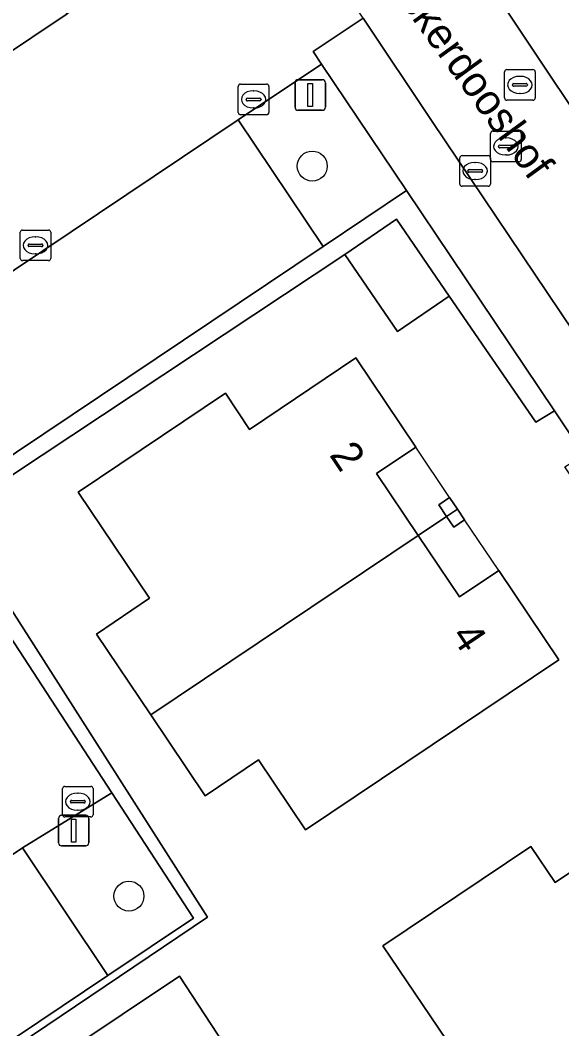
# Model space of a CAD drawing. Extents: x 158793 to 159888, y 384317 to 385256.
# Drawn here: x 159024.76 to 159042.44, y 384694.29 to 384727.22 of the extents above; entities that cross this region are included whole.
import ezdxf

# ---------------------------------------------------------------- set-up
doc = ezdxf.new("R2010")
doc.units = 0
for name, color, linetype in [('IMGEO_Boom', 7, 'Continuous'), ('IMGEO_Erf', 7, 'Continuous'), ('IMGEO_Groenvoorziening', 7, 'Continuous'), ('IMGEO_Haag', 7, 'Continuous'), ('IMGEO_Kolk', 7, 'Continuous'), ('IMGEO_Lichtmast', 7, 'Continuous'), ('IMGEO_Openbare_ruimte_label', 7, 'Continuous'), ('IMGEO_Pand', 7, 'Continuous'), ('IMGEO_Pand_nummerreeks', 7, 'Continuous'), ('IMGEO_Pand_overbouw', 7, 'Continuous'), ('IMGEO_Parkeervlak_open', 7, 'Continuous'), ('IMGEO_Rijbaan_lokaal_open', 7, 'Continuous'), ('IMGEO_Rioolput', 7, 'Continuous'), ('IMGEO_Voetpad_open', 7, 'Continuous')]:
    doc.layers.add(name, color=color, linetype=linetype)

msp = doc.modelspace()

# ---------------------------------------------------------------- linework, layer by layer
at = {"layer": 'IMGEO_Boom'}
for centre in [(159034.294, 384722.455), (159028.308, 384698.621)]:
    msp.add_circle(centre, 0.489, dxfattribs=at)
at = {"layer": 'IMGEO_Erf'}
msp.add_lwpolyline([(159055.318, 384693.517), (159052.491, 384697.775), (159053.123, 384698.213), (159052.175, 384699.623), (159051.584, 384699.252), (159048.706, 384703.383), (159047.007, 384702.243), (159045.317, 384704.764), (159043.638, 384707.269), (159045.328, 384708.423), (159042.543, 384712.634), (159043.163, 384713.033), (159042.202, 384714.463), (159041.598, 384714.096), (159038.77, 384718.208), (159037.078, 384717.054), (159035.359, 384719.573), (159022.492, 384711.051), (159024.718, 384707.573), (159030.87, 384697.932), (159016.999, 384688.587)], dxfattribs=at)
for points in [[(159040.385, 384709.248), (159042.345, 384706.334), (159034.075, 384700.783), (159032.538, 384703.066), (159030.794, 384701.892), (159029.02, 384704.535), (159027.246, 384707.177), (159028.983, 384708.347), (159026.647, 384711.814), (159031.457, 384715.04), (159032.247, 384713.86), (159035.716, 384716.191), (159037.675, 384713.278), (159036.397, 384712.419), (159037.756, 384710.399), (159039.106, 384708.393)], [(159039.269, 384710.907), (159038.917, 384710.67), (159038.679, 384711.019), (159038.424, 384711.393), (159038.781, 384711.633), (159039.034, 384711.257)], [(159047.656, 384698.482), (159046.366, 384697.618), (159047.711, 384695.583), (159049.055, 384693.548), (159050.34, 384694.411), (159052.295, 384691.502), (159043.979, 384685.926), (159042.461, 384688.214), (159040.71, 384687.044), (159038.89, 384689.755), (159037.159, 384692.334), (159038.938, 384693.537), (159036.601, 384696.993), (159041.436, 384700.241), (159042.229, 384699.061), (159045.709, 384701.391)], [(159036.569, 384683.938), (159034.328, 384682.412), (159035.518, 384680.598), (159032.519, 384678.557), (159030.179, 384682.029), (159028.896, 384681.167), (159027.613, 384680.304), (159030, 384676.764), (159027.005, 384674.748), (159025.717, 384676.65), (159023.432, 384675.127), (159022.331, 384676.771), (159021.158, 384675.986), (159017.982, 384680.739), (159020.712, 384682.584), (159021.88, 384683.374), (159019.249, 384687.3), (159026.926, 384692.448), (159026.219, 384693.503), (159029.956, 384696.009), (159033.245, 384690.989), (159032.277, 384690.34)]]:
    msp.add_lwpolyline(points, close=True, dxfattribs=at)
at = {"layer": 'IMGEO_Groenvoorziening'}
for points in [[(159031.875, 384723.961), (159034.645, 384719.834), (159037.367, 384721.658), (159034.599, 384725.777)], [(159035.359, 384719.573), (159037.05, 384720.727), (159038.77, 384718.208), (159041.598, 384714.096), (159042.202, 384714.463), (159037.367, 384721.658), (159034.645, 384719.834), (159021.882, 384711.279), (159024.421, 384707.105), (159027.752, 384701.991), (159030.413, 384697.906), (159027.614, 384696.029), (159017.072, 384688.957), (159016.845, 384688.805), (159016.999, 384688.587), (159030.87, 384697.932), (159024.718, 384707.573), (159022.492, 384711.051)], [(159027.752, 384701.991), (159024.836, 384700.201), (159027.614, 384696.029), (159030.413, 384697.906)]]:
    msp.add_lwpolyline(points, close=True, dxfattribs=at)
at = {"layer": 'IMGEO_Haag'}
msp.add_lwpolyline([(159037.367, 384721.658), (159034.645, 384719.834), (159021.882, 384711.279), (159024.421, 384707.105), (159027.752, 384701.991), (159030.413, 384697.906), (159027.614, 384696.029), (159017.072, 384688.957), (159016.845, 384688.805), (159016.999, 384688.587), (159030.87, 384697.932), (159024.718, 384707.573), (159022.492, 384711.051), (159035.359, 384719.573), (159037.05, 384720.727), (159038.77, 384718.208), (159041.598, 384714.096), (159042.202, 384714.463)], close=True, dxfattribs=at)
at = {"layer": 'IMGEO_Kolk'}
for p, q in [((159031.878, 384724.206), (159031.878, 384725.058)), ((159031.953, 384725.132), (159032.805, 384725.132)), ((159032.879, 384725.058), (159032.879, 384724.206)), ((159032.366, 384724.912), (159032.391, 384724.912)), ((159032.137, 384724.626), (159032.137, 384724.638)), ((159032.575, 384724.589), (159032.177, 384724.589)), ((159032.18, 384724.675), (159032.578, 384724.675)), ((159032.621, 384724.638), (159032.621, 384724.626)), ((159032.805, 384724.132), (159031.953, 384724.132)), ((159032.389, 384724.352), (159032.364, 384724.352)), ((159039.111, 384721.869), (159039.111, 384722.721)), ((159039.186, 384722.795), (159040.038, 384722.795)), ((159040.112, 384722.721), (159040.112, 384721.869)), ((159039.599, 384722.575), (159039.624, 384722.575)), ((159039.37, 384722.289), (159039.37, 384722.301)), ((159039.808, 384722.252), (159039.41, 384722.252)), ((159039.413, 384722.338), (159039.811, 384722.338)), ((159039.854, 384722.301), (159039.854, 384722.289)), ((159040.038, 384721.795), (159039.186, 384721.795)), ((159039.622, 384722.015), (159039.597, 384722.015)), ((159024.755, 384719.441), (159024.755, 384720.293)), ((159024.83, 384720.367), (159025.682, 384720.367)), ((159025.243, 384720.147), (159025.268, 384720.147)), ((159025.756, 384720.293), (159025.756, 384719.441)), ((159025.014, 384719.861), (159025.014, 384719.873)), ((159025.452, 384719.824), (159025.054, 384719.824)), ((159025.057, 384719.91), (159025.455, 384719.91)), ((159025.498, 384719.873), (159025.498, 384719.861)), ((159025.266, 384719.587), (159025.241, 384719.587)), ((159025.682, 384719.367), (159024.83, 384719.367)), ((159026.137, 384701.278), (159026.137, 384702.13)), ((159026.212, 384702.204), (159027.064, 384702.204)), ((159026.625, 384701.984), (159026.65, 384701.984)), ((159027.138, 384702.13), (159027.138, 384701.278)), ((159026.396, 384701.698), (159026.396, 384701.71)), ((159026.834, 384701.661), (159026.436, 384701.661)), ((159026.439, 384701.747), (159026.837, 384701.747)), ((159026.88, 384701.71), (159026.88, 384701.698)), ((159026.648, 384701.424), (159026.623, 384701.424)), ((159027.064, 384701.204), (159026.212, 384701.204))]:
    msp.add_line(p, q, dxfattribs=at)
for points in [[(159031.878, 384724.206), (159031.878, 384725.058)], [(159031.953, 384725.132), (159032.805, 384725.132)], [(159032.879, 384725.058), (159032.879, 384724.206)], [(159032.805, 384724.132), (159031.953, 384724.132)], [(159039.111, 384721.869), (159039.111, 384722.721)], [(159039.186, 384722.795), (159040.038, 384722.795)], [(159040.112, 384722.721), (159040.112, 384721.869)], [(159040.038, 384721.795), (159039.186, 384721.795)], [(159024.755, 384719.441), (159024.755, 384720.293)], [(159024.83, 384720.367), (159025.682, 384720.367)], [(159025.756, 384720.293), (159025.756, 384719.441)], [(159025.682, 384719.367), (159024.83, 384719.367)], [(159026.137, 384701.278), (159026.137, 384702.13)], [(159026.212, 384702.204), (159027.064, 384702.204)], [(159027.138, 384702.13), (159027.138, 384701.278)], [(159027.064, 384701.204), (159026.212, 384701.204)]]:
    msp.add_lwpolyline(points, dxfattribs=at)
for centre, radius, start, end in [((159031.955, 384725.056), 0.0765, 91.552, 178.448), ((159031.955, 384725.056), 0.0765, 91.552, 178.448), ((159032.803, 384725.056), 0.0765, 1.552, 88.448), ((159032.803, 384725.056), 0.0765, 1.552, 88.448), ((159032.177, 384724.635), 0.0403, 85.8775, 175.7526), ((159032.174, 384724.625), 0.0366, 178.938, 274.7102), ((159032.578, 384724.632), 0.043, 264.8664, 352.4533), ((159032.582, 384724.637), 0.0386, 1.7309, 96.639), ((159031.955, 384724.208), 0.0765, 181.552, 268.448), ((159031.955, 384724.208), 0.0765, 181.552, 268.448), ((159032.803, 384724.208), 0.0765, 271.552, 358.448), ((159032.803, 384724.208), 0.0765, 271.552, 358.448), ((159039.188, 384722.719), 0.0765, 91.552, 178.448), ((159039.188, 384722.719), 0.0765, 91.552, 178.448), ((159040.036, 384722.719), 0.0765, 1.552, 88.448), ((159040.036, 384722.719), 0.0765, 1.552, 88.448), ((159039.41, 384722.298), 0.0403, 85.8775, 175.7526), ((159039.407, 384722.288), 0.0366, 178.938, 274.7102), ((159039.811, 384722.295), 0.043, 264.8664, 352.4533), ((159039.815, 384722.3), 0.0386, 1.7309, 96.639), ((159039.188, 384721.871), 0.0765, 181.552, 268.448), ((159039.188, 384721.871), 0.0765, 181.552, 268.448), ((159040.036, 384721.871), 0.0765, 271.552, 358.448), ((159040.036, 384721.871), 0.0765, 271.552, 358.448), ((159024.832, 384720.291), 0.0765, 91.552, 178.448), ((159024.832, 384720.291), 0.0765, 91.552, 178.448), ((159025.68, 384720.291), 0.0765, 1.552, 88.448), ((159025.68, 384720.291), 0.0765, 1.552, 88.448), ((159025.054, 384719.87), 0.0403, 85.8775, 175.7526), ((159025.051, 384719.86), 0.0366, 178.938, 274.7102), ((159025.455, 384719.867), 0.043, 264.8664, 352.4533), ((159025.459, 384719.872), 0.0386, 1.7309, 96.639), ((159024.832, 384719.443), 0.0765, 181.552, 268.448), ((159024.832, 384719.443), 0.0765, 181.552, 268.448), ((159025.68, 384719.443), 0.0765, 271.552, 358.448), ((159025.68, 384719.443), 0.0765, 271.552, 358.448), ((159026.214, 384702.128), 0.0765, 91.552, 178.448), ((159026.214, 384702.128), 0.0765, 91.552, 178.448), ((159027.062, 384702.128), 0.0765, 1.552, 88.448), ((159027.062, 384702.128), 0.0765, 1.552, 88.448), ((159026.436, 384701.707), 0.0403, 85.8775, 175.7526), ((159026.433, 384701.697), 0.0366, 178.938, 274.7102), ((159026.837, 384701.704), 0.043, 264.8664, 352.4533), ((159026.841, 384701.709), 0.0386, 1.7309, 96.639), ((159026.214, 384701.28), 0.0765, 181.552, 268.448), ((159026.214, 384701.28), 0.0765, 181.552, 268.448), ((159027.062, 384701.28), 0.0765, 271.552, 358.448), ((159027.062, 384701.28), 0.0765, 271.552, 358.448)]:
    msp.add_arc(centre, radius, start, end, dxfattribs=at)
for centre, major_axis, ratio, start_param, end_param in [((159032.365, 384724.632), (-0.387, 0.002), 0.722429, 4.712389, 7.853982), ((159032.39, 384724.632), (-0.39, 0.002), 0.717154, 1.570796, 4.712389), ((159039.598, 384722.295), (-0.387, 0.002), 0.722429, 4.712389, 7.853982), ((159039.623, 384722.295), (-0.39, 0.002), 0.717154, 1.570796, 4.712389), ((159025.242, 384719.867), (-0.387, 0.002), 0.722429, 4.712389, 7.853982), ((159025.267, 384719.867), (-0.39, 0.002), 0.717154, 1.570796, 4.712389), ((159026.624, 384701.704), (-0.387, 0.002), 0.722429, 4.712389, 7.853982), ((159026.649, 384701.704), (-0.39, 0.002), 0.717154, 1.570796, 4.712389)]:
    msp.add_ellipse(centre, major_axis=major_axis, ratio=ratio, start_param=start_param, end_param=end_param, dxfattribs=at)
at = {"layer": 'IMGEO_Lichtmast'}
for p, q in [((159033.732, 384724.376), (159033.732, 384725.176)), ((159033.732, 384725.176), (159033.732, 384724.376)), ((159033.832, 384725.276), (159034.622, 384725.276)), ((159034.622, 384725.276), (159033.832, 384725.276)), ((159034.722, 384725.176), (159034.722, 384724.376)), ((159034.722, 384724.376), (159034.722, 384725.176)), ((159034.622, 384724.276), (159033.832, 384724.276)), ((159033.832, 384724.276), (159034.622, 384724.276)), ((159026.008, 384700.36), (159026.008, 384701.16)), ((159026.008, 384701.16), (159026.008, 384700.36)), ((159026.108, 384701.26), (159026.898, 384701.26)), ((159026.898, 384701.26), (159026.108, 384701.26)), ((159026.998, 384701.16), (159026.998, 384700.36)), ((159026.998, 384700.36), (159026.998, 384701.16)), ((159026.898, 384700.26), (159026.108, 384700.26)), ((159026.108, 384700.26), (159026.898, 384700.26))]:
    msp.add_line(p, q, dxfattribs=at)
for points in [[(159034.152, 384725.151), (159034.302, 384725.151), (159034.302, 384724.401), (159034.152, 384724.401), (159034.152, 384725.151)], [(159026.428, 384701.135), (159026.578, 384701.135), (159026.578, 384700.385), (159026.428, 384700.385), (159026.428, 384701.135)]]:
    msp.add_lwpolyline(points, dxfattribs=at)
for centre, start, end in [((159033.832, 384725.176), 90, 180), ((159033.832, 384725.176), 90, 180), ((159034.622, 384725.176), 0, 90), ((159034.622, 384725.176), 360, 90), ((159033.832, 384724.376), 180, 270), ((159033.832, 384724.376), 180, 270), ((159034.622, 384724.376), 270, 0), ((159034.622, 384724.376), 270, 0), ((159026.108, 384701.16), 90, 180), ((159026.108, 384701.16), 90, 180), ((159026.898, 384701.16), 0, 90), ((159026.898, 384701.16), 360, 90), ((159026.108, 384700.36), 180, 270), ((159026.108, 384700.36), 180, 270), ((159026.898, 384700.36), 270, 0), ((159026.898, 384700.36), 270, 0)]:
    msp.add_arc(centre, 0.1, start, end, dxfattribs=at)
at = {"layer": 'IMGEO_Pand'}
for points in [[(159037.05, 384720.727), (159035.359, 384719.573), (159037.078, 384717.054), (159038.77, 384718.208)], [(159037.675, 384713.278), (159035.716, 384716.191), (159032.247, 384713.86), (159031.457, 384715.04), (159026.647, 384711.814), (159028.983, 384708.347), (159027.246, 384707.177), (159029.02, 384704.535), (159037.756, 384710.399), (159036.397, 384712.419)], [(159038.781, 384711.633), (159038.424, 384711.393), (159038.679, 384711.019), (159039.034, 384711.257)], [(159039.034, 384711.257), (159038.679, 384711.019), (159038.917, 384710.67), (159039.269, 384710.907)], [(159042.345, 384706.334), (159040.385, 384709.248), (159039.106, 384708.393), (159037.756, 384710.399), (159029.02, 384704.535), (159030.794, 384701.892), (159032.538, 384703.066), (159034.075, 384700.783)], [(159046.366, 384697.618), (159047.656, 384698.482), (159045.709, 384701.391), (159042.229, 384699.061), (159041.436, 384700.241), (159036.601, 384696.993), (159038.938, 384693.537), (159037.159, 384692.334), (159038.89, 384689.755), (159047.711, 384695.583)], [(159026.979, 384686.789), (159029.561, 384688.519), (159032.277, 384690.34), (159033.245, 384690.989), (159029.956, 384696.009), (159026.219, 384693.503), (159026.926, 384692.448), (159019.249, 384687.3), (159021.88, 384683.374), (159024.41, 384685.069), (159027.613, 384680.304), (159028.896, 384681.167), (159030.179, 384682.029)]]:
    msp.add_lwpolyline(points, close=True, dxfattribs=at)
at = {"layer": 'IMGEO_Pand_overbouw'}
for points in [[(159037.675, 384713.278), (159036.397, 384712.419), (159037.756, 384710.399), (159038.679, 384711.019), (159039.034, 384711.257), (159038.781, 384711.633)], [(159039.034, 384711.257), (159038.679, 384711.019), (159037.756, 384710.399), (159039.106, 384708.393), (159040.385, 384709.248), (159039.269, 384710.907)]]:
    msp.add_lwpolyline(points, close=True, dxfattribs=at)
at = {"layer": 'IMGEO_Parkeervlak_open'}
for points in [[(159023.556, 384731.598), (159012.982, 384724.532), (159015.764, 384720.383), (159026.289, 384727.424)], [(159031.875, 384723.961), (159019.105, 384715.414), (159021.882, 384711.279), (159034.645, 384719.834)], [(159024.836, 384700.201), (159014.319, 384693.094), (159017.072, 384688.957), (159027.614, 384696.029)]]:
    msp.add_lwpolyline(points, close=True, dxfattribs=at)
at = {"layer": 'IMGEO_Rijbaan_lokaal_open'}
for points in [[(159060.297, 384733.489), (159063.063, 384729.38), (159064.002, 384730.015), (159061.224, 384734.114), (159055.804, 384742.112), (159059.106, 384744.363), (159058.367, 384745.484), (159057.651, 384745), (159056.734, 384744.381), (159055.036, 384743.235), (159054.18, 384742.657), (159056.921, 384738.516), (159042.211, 384728.554), (159040.655, 384727.511), (159044.027, 384722.47), (159045.584, 384723.571)], [(159031.875, 384723.961), (159034.599, 384725.777), (159034.326, 384726.199), (159035.952, 384727.281), (159033.174, 384731.422), (159031.541, 384730.299), (159031.257, 384730.722), (159029.8, 384729.773), (159027.59, 384728.294), (159026.289, 384727.424), (159015.764, 384720.383), (159012.842, 384718.427), (159016.136, 384713.472), (159019.105, 384715.414)], [(159024.836, 384700.201), (159027.752, 384701.991), (159024.421, 384707.105), (159021.48, 384705.149), (159008.765, 384696.51), (159006.073, 384694.696), (159006.349, 384694.266), (159004.736, 384693.195), (159007.469, 384689.118), (159009.103, 384690.19), (159009.384, 384689.772), (159010.828, 384690.734), (159013.039, 384692.228), (159014.319, 384693.094)]]:
    msp.add_lwpolyline(points, close=True, dxfattribs=at)
msp.add_lwpolyline([(159035.952, 384727.281), (159038.211, 384723.914), (159052.049, 384703.346), (159059.563, 384692.109), (159060.67, 384690.454), (159064.041, 384692.712), (159062.417, 384695.153), (159060.196, 384698.421), (159054.304, 384707.184), (159053.877, 384707.82), (159053.009, 384709.11), (159052.602, 384709.716), (159046.79, 384718.36), (159044.027, 384722.47), (159040.655, 384727.511)], dxfattribs=at)
at = {"layer": 'IMGEO_Rioolput'}
for p, q in [((159040.575, 384724.679), (159040.575, 384725.531)), ((159040.65, 384725.605), (159041.502, 384725.605)), ((159041.063, 384725.385), (159041.088, 384725.385)), ((159041.576, 384725.531), (159041.576, 384724.679)), ((159040.834, 384725.099), (159040.834, 384725.111)), ((159041.272, 384725.062), (159040.874, 384725.062)), ((159040.877, 384725.148), (159041.275, 384725.148)), ((159041.318, 384725.111), (159041.318, 384725.099)), ((159041.086, 384724.825), (159041.061, 384724.825)), ((159041.502, 384724.605), (159040.65, 384724.605)), ((159040.116, 384722.671), (159040.116, 384723.523)), ((159040.191, 384723.597), (159041.043, 384723.597)), ((159040.604, 384723.377), (159040.629, 384723.377)), ((159041.117, 384723.523), (159041.117, 384722.671)), ((159040.375, 384723.091), (159040.375, 384723.103)), ((159040.813, 384723.054), (159040.415, 384723.054)), ((159040.418, 384723.14), (159040.816, 384723.14)), ((159040.859, 384723.103), (159040.859, 384723.091)), ((159040.627, 384722.817), (159040.602, 384722.817)), ((159041.043, 384722.597), (159040.191, 384722.597))]:
    msp.add_line(p, q, dxfattribs=at)
for points in [[(159040.575, 384724.679), (159040.575, 384725.531)], [(159040.65, 384725.605), (159041.502, 384725.605)], [(159041.576, 384725.531), (159041.576, 384724.679)], [(159041.502, 384724.605), (159040.65, 384724.605)], [(159040.116, 384722.671), (159040.116, 384723.523)], [(159040.191, 384723.597), (159041.043, 384723.597)], [(159041.117, 384723.523), (159041.117, 384722.671)], [(159041.043, 384722.597), (159040.191, 384722.597)]]:
    msp.add_lwpolyline(points, dxfattribs=at)
for centre, radius, start, end in [((159040.652, 384725.529), 0.0765, 91.552, 178.448), ((159040.652, 384725.529), 0.0765, 91.552, 178.448), ((159041.5, 384725.529), 0.0765, 1.552, 88.448), ((159041.5, 384725.529), 0.0765, 1.552, 88.448), ((159040.874, 384725.108), 0.0403, 85.8775, 175.7526), ((159040.871, 384725.098), 0.0366, 178.938, 274.7102), ((159041.275, 384725.105), 0.043, 264.8664, 352.4533), ((159041.279, 384725.11), 0.0386, 1.7309, 96.639), ((159040.652, 384724.681), 0.0765, 181.552, 268.448), ((159040.652, 384724.681), 0.0765, 181.552, 268.448), ((159041.5, 384724.681), 0.0765, 271.552, 358.448), ((159041.5, 384724.681), 0.0765, 271.552, 358.448), ((159040.193, 384723.521), 0.0765, 91.552, 178.448), ((159040.193, 384723.521), 0.0765, 91.552, 178.448), ((159041.041, 384723.521), 0.0765, 1.552, 88.448), ((159041.041, 384723.521), 0.0765, 1.552, 88.448), ((159040.415, 384723.1), 0.0403, 85.8775, 175.7526), ((159040.412, 384723.09), 0.0366, 178.938, 274.7102), ((159040.816, 384723.097), 0.043, 264.8664, 352.4533), ((159040.82, 384723.102), 0.0386, 1.7309, 96.639), ((159040.193, 384722.673), 0.0765, 181.552, 268.448), ((159040.193, 384722.673), 0.0765, 181.552, 268.448), ((159041.041, 384722.673), 0.0765, 271.552, 358.448), ((159041.041, 384722.673), 0.0765, 271.552, 358.448)]:
    msp.add_arc(centre, radius, start, end, dxfattribs=at)
for centre, major_axis, ratio, start_param, end_param in [((159041.062, 384725.105), (-0.387, 0.002), 0.722429, 4.712389, 7.853982), ((159041.087, 384725.105), (-0.39, 0.002), 0.717154, 1.570796, 4.712389), ((159040.603, 384723.097), (-0.387, 0.002), 0.722429, 4.712389, 7.853982), ((159040.628, 384723.097), (-0.39, 0.002), 0.717154, 1.570796, 4.712389)]:
    msp.add_ellipse(centre, major_axis=major_axis, ratio=ratio, start_param=start_param, end_param=end_param, dxfattribs=at)
at = {"layer": 'IMGEO_Voetpad_open'}
msp.add_lwpolyline([(159038.211, 384723.914), (159035.952, 384727.281), (159034.326, 384726.199), (159034.599, 384725.777), (159037.367, 384721.658), (159042.202, 384714.463), (159043.163, 384713.033), (159052.175, 384699.623), (159053.123, 384698.213), (159056.671, 384692.933), (159057.387, 384691.831), (159057.126, 384690.444), (159059.563, 384692.109), (159052.049, 384703.346)], close=True, dxfattribs=at)

# ---------------------------------------------------------------- texts
at = {"layer": 'IMGEO_Openbare_ruimte_label'}
msp.add_text('Maskerdooshof', height=1, rotation=306.0105, dxfattribs=at).set_placement((159036.041, 384729.332))
at = {"layer": 'IMGEO_Pand_nummerreeks'}
for s, rotation, p in [('2', 303.9189, (159034.832, 384713.026)), ('4', 303.9246, (159038.805, 384707.118))]:
    msp.add_text(s, height=1, rotation=rotation, dxfattribs=at).set_placement(p)

doc.saveas('drawing.dxf')
